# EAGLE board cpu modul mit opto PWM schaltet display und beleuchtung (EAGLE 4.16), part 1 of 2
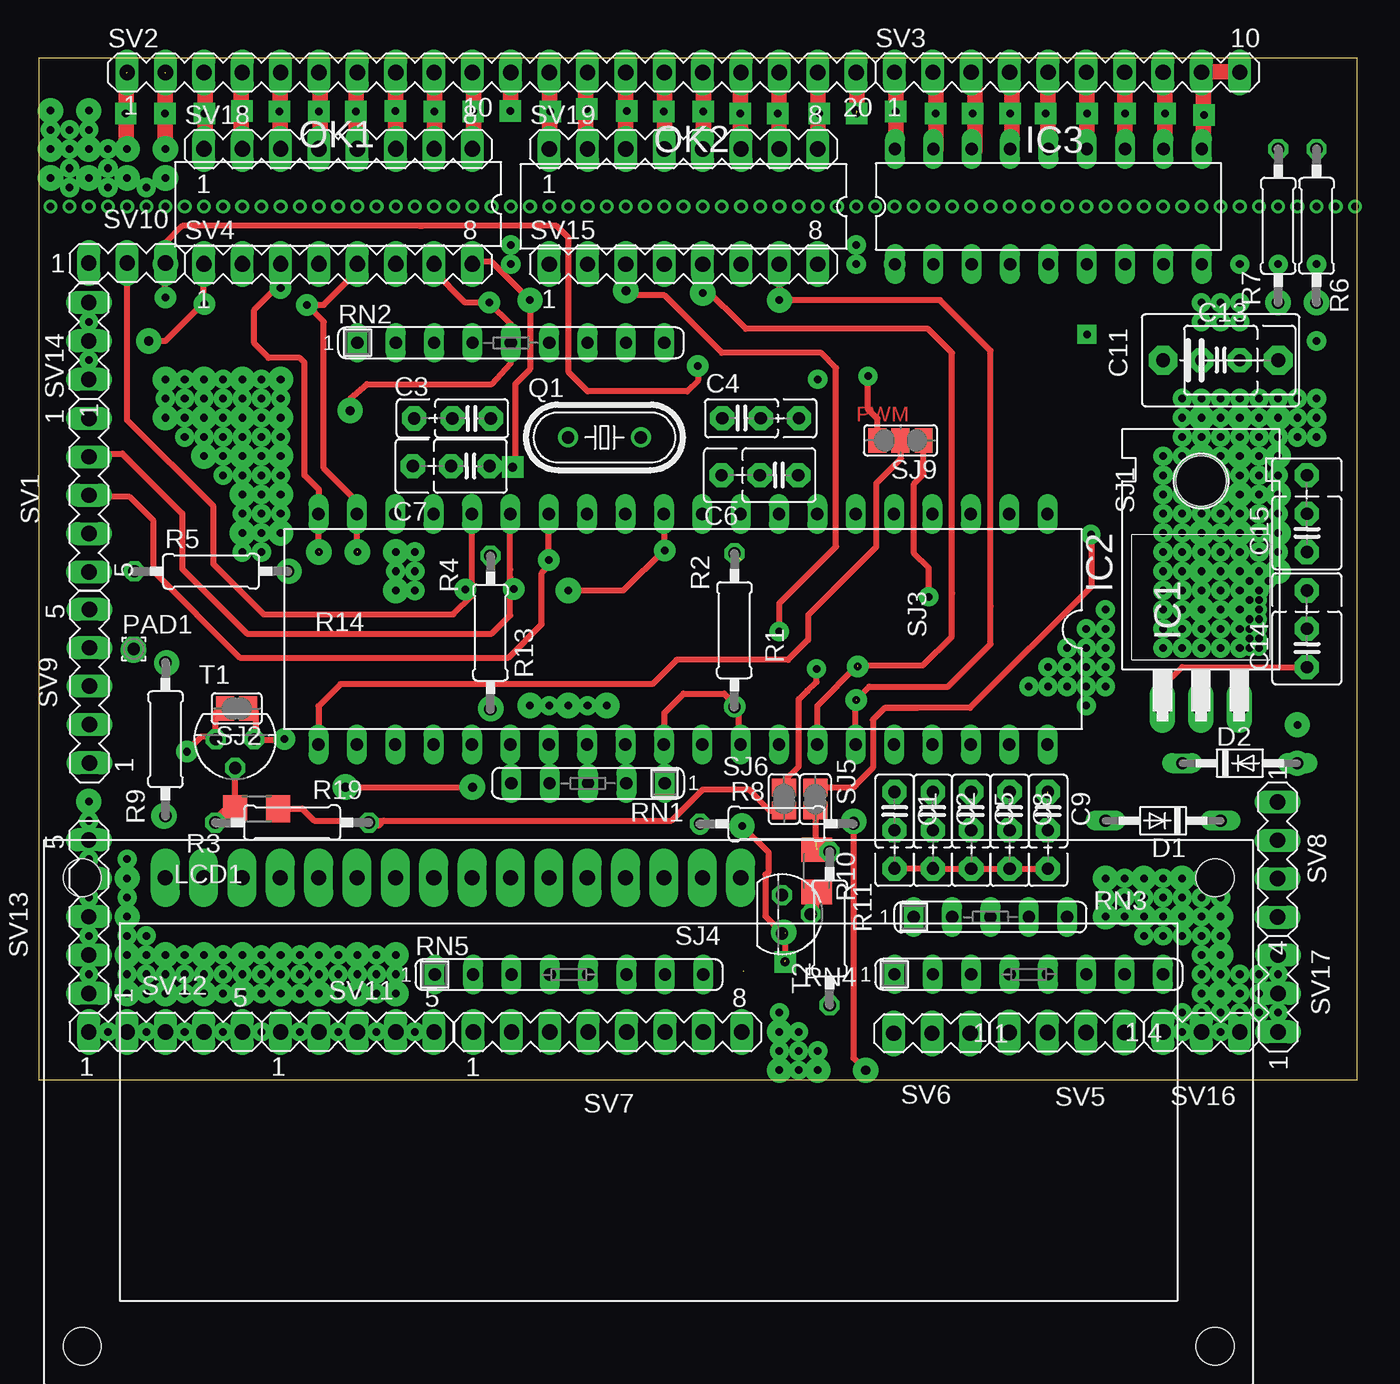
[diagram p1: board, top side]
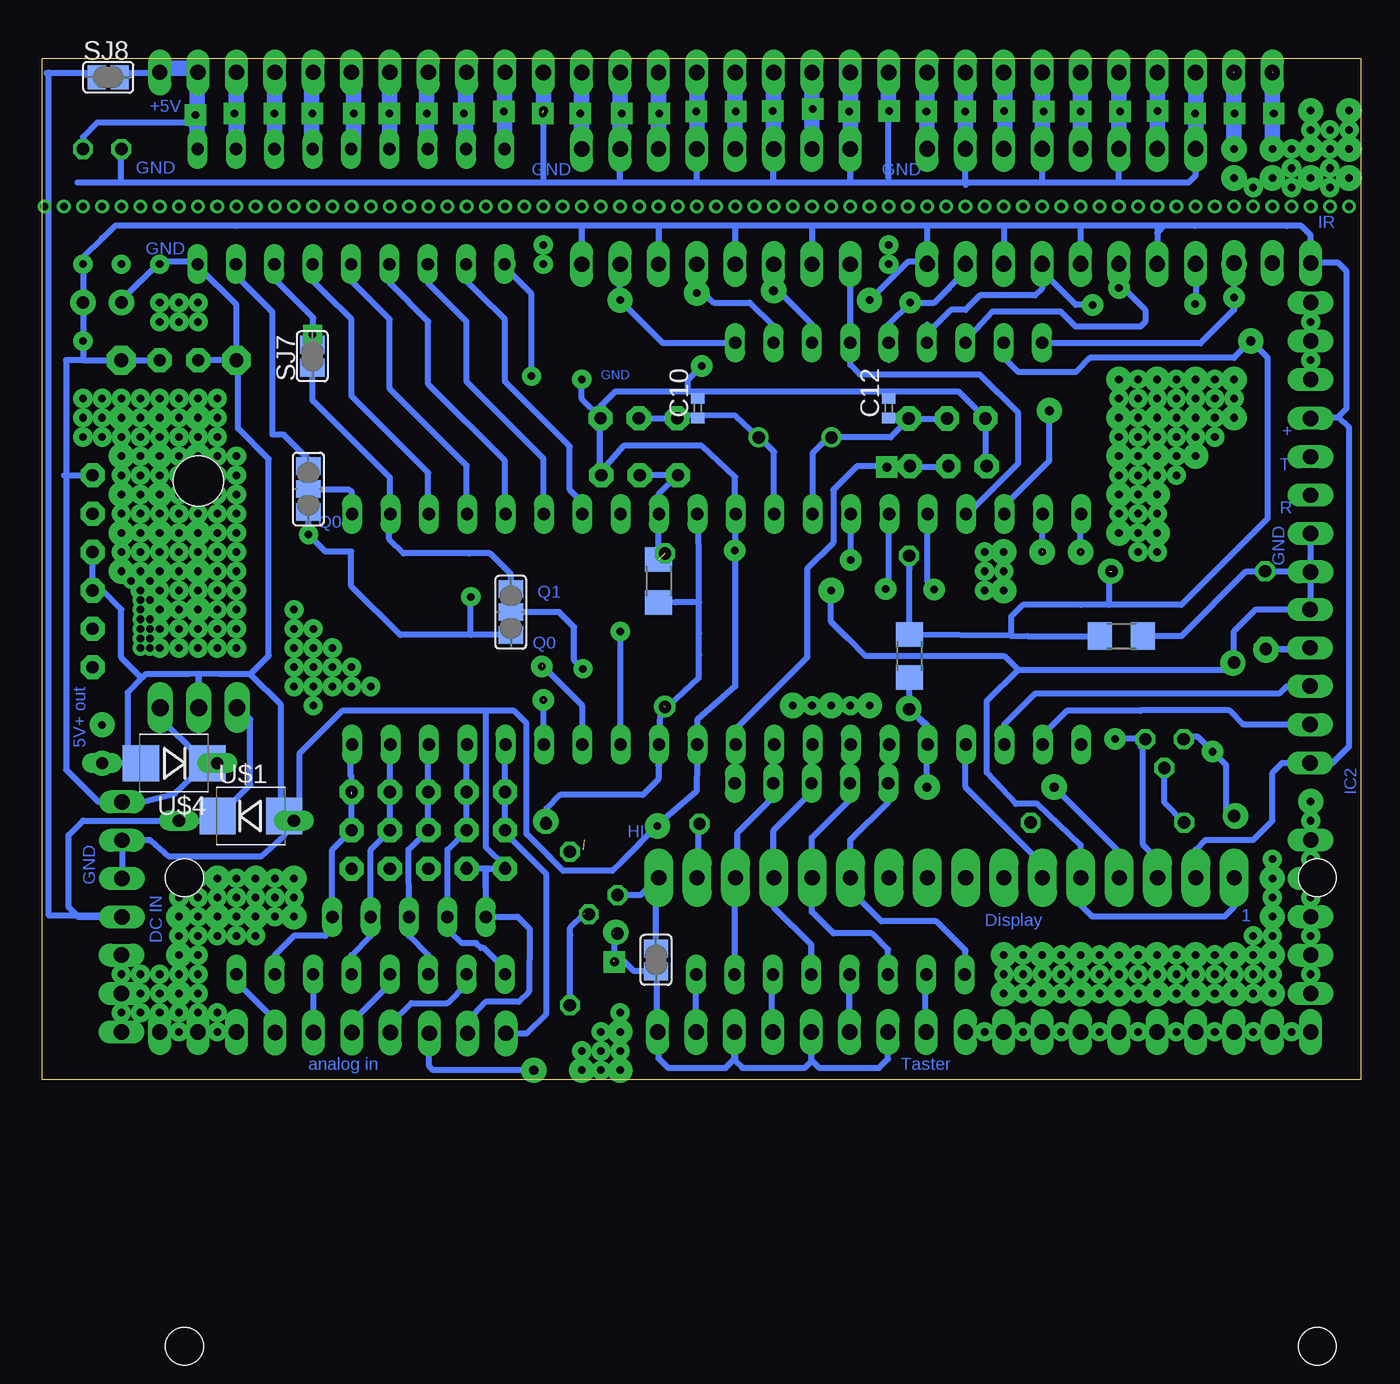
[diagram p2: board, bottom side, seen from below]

Size 87.3 x 67.62 mm. Coordinates in mm from the lower left corner, seen from the top.
Outline: 0,0 87.3,0 87.3,67.62 0,67.62 0,0
Copper layers (1*16): Top 0.035mm / dielectric 1.5mm / Bottom 0.035mm
Design rules "default": minimum track width 10mil, minimum drill 24mil, track to track 8mil, track to pad 8mil, pad to pad 8mil, via to via 8mil, smd to smd 8mil, copper to edge 40mil, drill to drill 8mil, minimum pad ring 10mil, minimum via ring 8mil, stop-mask expansion 4mil, vias tented up to drill 0mil, thermal gap 10mil
Net classes: 0 default: width 0.406 mm, drill 0.254 mm

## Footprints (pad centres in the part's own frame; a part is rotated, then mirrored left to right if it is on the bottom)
C2.5/5-2 = drill 0.813 pad 1.6 octagon: 1 -1.27,0; 2 1.27,0; 3 3.81,0
C2.5/5-4 = drill 0.813 pad 1.6 octagon: 1 -1.27,0; 2 1.27,0; 3 3.81,0
C1005 = smd 0.7 x 0.9: 1 -0.65,0; 2 0.65,0
C7.5B6 = drill 0.914 pad 1.905 octagon: 1 -3.81,0; 2 3.81,0
C2.5/5-5 = drill 0.813 pad 1.6 octagon: 1 -1.27,0; 2 1.27,0; 3 3.81,0
DO34-7 = drill 0.813 long: A 3.81,0; C -3.81,0
TO220H = drill 1.118 long: 1 -2.54,-10.16; 2 0,-10.16; 3 2.54,-10.16 | hole 3.302: 0,4.826
DIL40 = drill 0.813 long: 1 -24.13,-7.62; 2 -21.59,-7.62; 3 -19.05,-7.62; 4 -16.51,-7.62; 5 -13.97,-7.62; 6 -11.43,-7.62; 7 -8.89,-7.62; 8 -6.35,-7.62; 9 -3.81,-7.62; 10 -1.27,-7.62; 11 1.27,-7.62; 12 3.81,-7.62; 13 6.35,-7.62; 14 8.89,-7.62; 15 11.43,-7.62; 16 13.97,-7.62; 17 16.51,-7.62; 18 19.05,-7.62; 19 21.59,-7.62; 20 24.13,-7.62; 21 24.13,7.62; 22 21.59,7.62; 23 19.05,7.62; 24 16.51,7.62; 25 13.97,7.62; 26 11.43,7.62; 27 8.89,7.62; 28 6.35,7.62; 29 3.81,7.62; 30 1.27,7.62; 31 -1.27,7.62; 32 -3.81,7.62; 33 -6.35,7.62; 34 -8.89,7.62; 35 -11.43,7.62; 36 -13.97,7.62; 37 -16.51,7.62; 38 -19.05,7.62; 39 -21.59,7.62; 40 -24.13,7.62
DIL18 = drill 0.813 long: 1 -10.16,-3.81; 2 -7.62,-3.81; 3 -5.08,-3.81; 4 -2.54,-3.81; 5 0,-3.81; 6 2.54,-3.81; 7 5.08,-3.81; 8 7.62,-3.81; 9 10.16,-3.81; 10 10.16,3.81; 11 7.62,3.81; 12 5.08,3.81; 13 2.54,3.81; 14 0,3.81; 15 -2.54,3.81; 16 -5.08,3.81; 17 -7.62,3.81; 18 -10.16,3.81
HY-1602F = drill 1 pad 1.93 long: 1 2.54,0; 2 5.08,0; 3 7.62,0; 4 10.16,0; 5 12.7,0; 6 15.24,0; 7 17.78,0; 8 20.32,0; 9 22.86,0; 10 25.4,0; 11 27.94,0; 12 30.48,0; 13 33.02,0; 14 35.56,0; 15 38.1,0; 16 40.64,0 | hole 2.5: -2.96,0; 72.04,0; -2.96,-31; 72.04,-31
DIL16 = drill 0.813 octagon: 1 -8.89,-3.81; 2 -6.35,-3.81; 3 -3.81,-3.81; 4 -1.27,-3.81; 5 1.27,-3.81; 6 3.81,-3.81; 7 6.35,-3.81; 8 8.89,-3.81; 9 8.89,3.81; 10 6.35,3.81; 11 3.81,3.81; 12 1.27,3.81; 13 -1.27,3.81; 14 -3.81,3.81; 15 -6.35,3.81; 16 -8.89,3.81
1,6/0,8 = drill 0.813 pad 1.6 octagon: 1 0,0
HC49/S = drill 0.813 round: 1 -2.413,0; 2 2.413,0
R1206 = smd 1.6 x 1.803: 1 -1.422,0; 2 1.422,0
0207/10 = drill 0.813 octagon: 1 -5.08,0; 2 5.08,0
M1206 = smd 1.6 x 2: 1 -1.4,0; 2 1.4,0
SIL5 = drill 0.813 long: 1 -5.08,0; 2 -2.54,0; 3 0,0; 4 2.54,0; 5 5.08,0
SIL9 = drill 0.813 long: 1 -10.16,0; 2 -7.62,0; 3 -5.08,0; 4 -2.54,0; 5 0,0; 6 2.54,0; 7 5.08,0; 8 7.62,0; 9 10.16,0
SIL8 = drill 0.813 long: 1 -8.89,0; 2 -6.35,0; 3 -3.81,0; 4 -1.27,0; 5 1.27,0; 6 3.81,0; 7 6.35,0; 8 8.89,0
SJ_2 = smd 1.168 x 1.6: 1 -1.524,0; 2 0,0; 3 1.524,0
SJ = smd 1.168 x 1.6: 1 -0.762,0; 2 0.762,0
MA05-1 = drill 1.016 long: 1 -5.08,0; 2 -2.54,0; 3 0,0; 4 2.54,0; 5 5.08,0
MA20-1 = drill 1.016 long: 1 -24.13,0; 2 -21.59,0; 3 -19.05,0; 4 -16.51,0; 5 -13.97,0; 6 -11.43,0; 7 -8.89,0; 8 -6.35,0; 9 -3.81,0; 10 -1.27,0; 11 1.27,0; 12 3.81,0; 13 6.35,0; 14 8.89,0; 15 11.43,0; 16 13.97,0; 17 16.51,0; 18 19.05,0; 19 21.59,0; 20 24.13,0
MA10-1 = drill 1.016 long: 1 -11.43,0; 2 -8.89,0; 3 -6.35,0; 4 -3.81,0; 5 -1.27,0; 6 1.27,0; 7 3.81,0; 8 6.35,0; 9 8.89,0; 10 11.43,0
MA08-1 = drill 1.016 long: 1 -8.89,0; 2 -6.35,0; 3 -3.81,0; 4 -1.27,0; 5 1.27,0; 6 3.81,0; 7 6.35,0; 8 8.89,0
MA04-1 = drill 1.016 long: 1 -3.81,0; 2 -1.27,0; 3 1.27,0; 4 3.81,0
MA03-1 = drill 1.016 long: 1 -2.54,0; 2 0,0; 3 2.54,0
TO92 = drill 0.813 octagon: 1 1.27,0; 2 0,1.905; 3 -1.27,0
SMB = smd 2.4 x 2.4: A 2.2,0; C -2.2,0

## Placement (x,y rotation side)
C1  [C2.5/5-2]  56.67,17.78 270 top
C2  [C2.5/5-2]  59.21,17.78 270 top
C3  22pf  [C2.5/5-2]  28.67,43.76 180 top
C4  22pf  [C2.5/5-2]  46.54,43.78 0 top
C5  [C2.5/5-2]  61.75,17.78 270 top
C6  100n  [C2.5/5-4]  49.02,40.01 180 top
C7  100n  [C2.5/5-4]  28.59,40.61 180 top
C8  [C2.5/5-2]  64.29,17.78 270 top
C9  [C2.5/5-2]  66.83,17.78 270 top
C10  [C1005]  43.9,44.45 90 bottom
C11  [C7.5B6]  78.26,47.62 0 top
C12  [C1005]  31.26,44.45 90 bottom
C13  [C2.5/5-5]  78.26,47.62 0 top
C14  [C2.5/5-5]  83.97,28.57 90 top
C15  [C2.5/5-5]  83.97,36.19 90 top
D1  BAT81  [DO34-7]  74.45,17.14 180 top
D2  BAT81  [DO34-7]  79.53,20.95 0 top
IC1  7805T  [TO220H]  76.95,34.79 0 top
IC2  MEGA163LP  [DIL40]  42.66,29.81 180 top
IC3  [DIL18]  66.86,57.78 0 top
LCD1  LCD_2X16  [HY-1602F]  5.85,13.37 0 top
OK1  PC847  [DIL16]  19.84,57.94 180 top
OK2  PC847  [DIL16]  42.7,57.78 180 top
PAD1  [1,6/0,8]  6.31,28.5 0 top
Q1  [HC49/S]  37.47,42.51 0 top
R1  10k  [R1206]  46.5,33 90 bottom
R2  [0207/10]  46.07,29.75 270 top
R3  [0207/10]  16.79,17.02 180 top
R4  [0207/10]  29.92,29.6 270 top
R5  4K7  [0207/10]  11.42,33.65 0 top
R6  0  [0207/10]  84.61,56.51 90 top
R7  0R  [0207/10]  82.07,56.51 270 top
R8  47R  [0207/10]  48.87,16.94 0 top
R9  220R  [0207/10]  8.41,22.54 90 top
R10  [M1206]  51.51,13.82 270 top
R11  10K  [0207/10]  52.37,10.01 270 top
R13  1K  [R1206]  29.9,28.04 90 bottom
R14  4K7  [R1206]  15.87,29.36 180 bottom
R19  10K  [R1206]  14.44,17.93 180 top
RN1  100K  [SIL5]  36.38,19.62 180 top
RN2  10K  [SIL9]  31.27,48.77 0 top
RN3  4K7  [SIL5]  63.02,10.76 0 top
RN4  4K7  [SIL8]  65.56,6.98 0 top
RN5  [SIL8]  35.12,6.96 0 top
SJ1  [SJ_2]  69.69,39.1 270 bottom
SJ2  [SJ]  13.12,24.56 180 top
SJ3  [SJ_2]  56.28,30.95 90 bottom
SJ4  [SJ]  46.67,7.93 90 bottom
SJ5  [SJ]  51.43,18.57 90 top
SJ6  [SJ]  49.36,18.58 270 top
SJ7  [SJ]  69.42,47.88 90 bottom
SJ8  [SJ]  82.94,66.35 0 bottom
SJ9  [SJ_2]  57.06,42.31 180 top
SV1  [MA05-1]  3.33,38.69 270 top
SV2  [MA20-1]  30,66.66 0 top
SV3  [MA10-1]  68.1,66.67 0 top
SV4  [MA08-1]  19.84,53.97 0 top
SV5  [MA04-1]  68.08,3.12 0 top
SV6  [MA03-1]  59.15,3.07 180 top
SV7  [MA08-1]  37.67,3.15 0 top
SV8  [MA04-1]  82.02,14.58 270 top
SV9  [MA05-1]  3.37,26.05 90 top
SV10  [MA03-1]  5.87,54.05 0 top
SV11  [MA05-1]  21.11,3.17 0 top
SV12  [MA05-1]  8.41,3.17 0 top
SV13  [MA05-1]  3.33,10.79 90 top
SV14  [MA03-1]  3.33,48.89 90 top
SV15  [MA08-1]  42.7,53.97 0 top
SV16  [MA03-1]  76.99,3.17 0 top
SV17  [MA03-1]  82.07,5.71 90 top
SV18  [MA08-1]  19.84,61.59 0 top
SV19  [MA08-1]  42.7,61.59 0 top
T1  BC547  [TO92]  13.01,22.54 180 top
T2  BC547  [TO92]  49.22,10.95 270 top
U$1  [SMB]  73.49,17.46 0 bottom
U$4  [SMB]  78.57,20.95 180 bottom

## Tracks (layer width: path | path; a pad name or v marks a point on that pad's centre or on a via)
GND
  Top 0: C2.3 59.22,13.96 59.26,14 59.3,13.96 | 59.3,13.96 C5.3 | C5.3 C8.3 | C8.3 C9.3 | C5.3 C8.3 | C5.3 61.67,13.96 61.65,13.94 | 59.3,13.96 59.29,13.96 | C5.3 59.29,13.96 | 59.29,13.96 59.26,13.94
  Bottom 0.406: 57.94,13.96 C1.3 | 57.94,12.7 57.94,13.96 | 57.94,13.96 C2.3
N$1
  Bottom 0: C10.1 43.9,43.85 44.02,43.97 45.24,43.97
  Bottom 0.406: C4.1 45.27,43.94 45.24,43.97 41.39,43.93 Q1.2 39.84,42.54 38.85,41.55 IC2.12
N$2  (1 unrouted)
  Bottom 0.406: C6.3 45.23,40.01 46.47,38.76 IC2.9 46.51,37.46 | R1.2 46.51,37.46 | 46.51,37.46
N$3
  Bottom 0: C3.1 29.96,43.77 29.96,43.76 29.99,43.79 C12.1
  Bottom 0.406: IC2.13 36.3,38.63 36.3,41.47 35.24,42.54 35.2,42.51 Q1.1 31.14,42.51 29.88,43.77 | 29.88,43.77 29.84,43.81 | C3.1 29.88,43.77
N$4  (via drill 0.5 pad 1.27, 0.6 pad 1.68)
  Top 0.406: OK2.11 v38.89,52.22 39.2,51.91 41.43,51.91 45.24,48.1 51.8,48.1 52.8,47.1 52.8,35.29 | 52.8,35.29 | 52.8,35.29 49.04,31.53 v49.04,29.67 v49.04,29.66 | v49.04,29.66 49.01,29.64 | v49.04,29.66
  Bottom 0.406: RN2.7 36.35,50.01 38.89,52.54 v38.89,52.22 | v49.04,29.66 49.04,29.63 49.01,29.61 IC2.33
N$5
  Top 0.406: SJ2.2 12.01,24.56 11.72,24.27 11.72,22.51 11.74,22.49 | 11.74,22.49 11.78,22.45 | T1.1 11.74,22.49
  Bottom 0.406: R9.1 8.92,17.5 8.92,20.82 10.79,22.7 11.74,22.7 | 11.74,22.7 | 11.74,22.7 T1.1
N$6  (via drill 0.5 pad 1.68)
  Top 0.406: 43.97,52.54 46.83,49.68 58.89,49.68 60.48,48.1 60.48,32.2 60.49,32.19 60.46,32.15 60.46,29.33 58.55,27.42 54.23,27.42 51.55,24.74 IC2.34 | 43.97,52.54 OK2.13 | 43.97,52.54 v43.97,52.06
  Bottom 0.406: RN2.8 38.89,49.85 40.48,51.43 42.86,51.43 43.97,52.54 43.97,53.81 | v43.97,52.06 43.97,53.81 | 43.97,53.81 OK2.13
N$7
  Bottom 0.406: RN5.7 41.43,8.15 41.43,11.81 LCD1.14 41.31,13.37 41.27,13.33 41.27,16.35 38.92,18.7 RN1.2 38.92,22.19 38.89,22.22 IC2.29
N$8
  Bottom 0.406: IC2.28 36.35,22.22 36.38,22.19 RN1.3 36.38,19.02 38.89,16.5 38.89,13.33 38.87,13.35 LCD1.13 38.87,13.19 38.89,13.17 38.89,11.43 36.39,8.93 RN5.5
N$9
  Bottom 0.406: IC2.27 33.81,22.22 33.84,22.19 RN1.4 33.84,18.54 36.35,16.03 36.35,13.49 36.47,13.37 LCD1.12 36.33,13.35 36.35,13.33 36.35,11.11 34.92,9.68 32.38,9.68 31.31,8.61 RN5.3
N$10
  Bottom 0.406: IC2.26 31.27,21.15 31.27,20.75 RN1.5 31.3,18.38 33.81,15.87 33.81,13.33 | 33.81,13.33 33.79,13.35 LCD1.11 | 33.81,13.33 33.81,12.54 31.74,10.47 28.09,10.47 26.19,8.57 26.19,7.14 26.35,6.98 26.33,6.96 RN5.1
N$11
  Bottom 0.406: R8.1 43.87,16.68 43.87,15.06 LCD1.15
N$12
  Top 0.406: SJ2.1 14.2,24.56 14.4,24.36 14.4,22.69 14.28,22.57 T1.3
  Bottom 0.406: LCD1.3 13.47,13.35 13.49,13.33 13.49,14.6 14.44,15.55 14.44,22.22 14.28,22.38 | 14.28,22.38 14.6,22.06 | 14.28,22.38 | 14.28,22.38 T1.3
N$13
  Bottom 0.406: 59.07,34.84 59.03,34.84 | 59.07,34.84 63.4,34.84 64.33,35.77 64.33,37.47 64.3,37.43 IC2.2 64.29,37.46 64.29,39.84 69.37,44.93 69.39,44.93 69.39,47.12 SJ7.1 69.42,48.66 | SJ3.3 56.28,33.45 57.67,34.83 59.07,34.83 59.07,34.84 | IC3.7 71.94,53.88 71.94,53.87 71.94,53 69.36,50.42 69.36,48.64 SJ7.2 69.42,48.66 | 69.42,48.66 69.39,48.69
N$14
  Bottom 0.406: LCD1.6 21.09,14.26 26.19,19.36 26.19,22.38 26.15,22.34 IC2.24
N$15
  Top 0: R3.2 11.71,17.3 12.46,18.06 12.87,18.06 13.02,17.91 R19.2
  Top 0.406: R19.2 | R19.2 T1.2 | R19.2
N$16
  Bottom 0.406: 10.9,51.36 10.9,54.12
N$17  (via drill 0.6 pad 1.68)  (1 unrouted)
  Top 0.406: v7.3,48.89 8.41,48.89 10.95,51.43 OK1.9 | OK1.9
  Bottom 0: 29.94,34.7 R4.1 29.92,34.65 29.9,34.63
  Bottom 0.406: 23.16,29.38 R13.2 29.9,34.73 | 23.16,29.38 22.06,29.36 R14.2 | R14.2 | R14.2 | 23.16,29.38 23.16,30.64 22.38,31.43 16.66,31.43 | 16.66,31.43 11.9,31.43 6.18,37.14 6.18,47.78 v7.3,48.89 8.41,47.78 17.93,47.78 18.89,46.83 22.69,46.83 23.65,47.78 RN2.2 | 16.66,31.43 16.66,33.65 | 16.66,31.43 18.57,31.43 | 29.9,34.73 29.92,34.71 R4.1 | 29.9,34.73 29.89,34.74
N$18
  Bottom 0.406: IC2.3 61.71,37.49 61.59,37.62 61.75,37.78 61.75,40.16 66.83,45.24 66.83,50.32 68.57,52.06 | 68.57,52.06 | 68.57,52.06 69.37,52.86 69.37,53.97 IC3.6
N$19
  Top 0.406: IC2.14 33.77,34.09 33.31,33.52 33.31,30.16 31.11,27.93 13.33,27.93 7.61,33.65 7.61,36.98 6.03,38.57 3.49,38.57 3.33,38.72 | 3.33,38.72 3.33,38.73 | 3.33,38.72 SV1.3
N$20
  Bottom 0.406: IC2.4 59.21,37.46 59.21,40.63 64.29,45.72 64.29,50.32 66.03,52.06 | 66.03,52.06 | 66.03,52.06 66.83,52.86 66.83,53.97 IC3.5
N$21  (via drill 0.5 pad 1.68)
  Top 0.406: 49.05,52.38 49.84,51.59 59.68,51.59 63.02,48.25 63.02,31.34 63.03,31.33 63.03,28.83 60.21,26.02 54.99,26.02 54.09,25.12 IC2.35 | 49.05,52.38 OK2.15 | 49.05,52.38 v49.05,51.59
  Bottom 0.406: RN2.9 46.23,48.77 v49.05,51.59 49.05,53.65 | 49.05,53.65 OK2.15 49.05,53.65
N$22
  Top 0.406: IC2.15 31.23,33.77 31.23,33.27 31.23,30.73 30.01,29.52 13.81,29.52 9.52,33.81 9.52,37.46 5.55,41.43 3.65,41.43 3.44,41.22 SV1.2
N$23
  Bottom 1.016: 56.7,61.7 56.7,66.65 56.63,66.72
N$24
  Top 0.406: 26.19,53.65 26.19,54.13
N$25
  Bottom 0.406: IC2.5 56.67,37.46 56.67,40.95 61.75,46.04 61.75,50.17 64.29,52.7 64.29,53.81 64.45,53.97 IC3.4
N$26
  Bottom 0.406: IC2.6 54,37.43 53.97,37.46 54.13,37.62 54.13,41.11 59.21,46.2 59.21,50.17 61.75,52.7 61.75,53.81 61.78,53.84 IC3.3
N$27
  Bottom 0.406: 52.54,42.06 56.67,46.2 56.67,50.32 58.41,52.06 | 52.54,42.06 | 52.54,42.06 52.38,41.9 52.38,39.05 51.59,38.25 51.59,37.62 51.75,37.46 51.72,37.43 IC2.7 | 58.41,52.06 | 58.41,52.06 59.21,52.86 59.21,53.97 IC3.2
N$28  (via drill 0.5 pad 1.42)
  other vias: 10.97,51.34
N$29
  Bottom 0.406: 26.19,53.65 26.19,54.13
N$30
  Bottom 0.406: 38.89,52.38 38.89,53.97
N$31
  Bottom 0.406: 33.97,53.97 33.91,54.03 | 33.97,53.97 33.81,53.82 RN2.6 33.81,47.31 33.17,46.67 25.24,46.67 22.69,44.13 22.69,40.79 26.06,37.43 IC2.17 | 33.97,53.97 OK2.9 | 33.97,53.97
N$32  (1 unrouted)
  Bottom 0.406: IC2.40 66.87,21.31 66.87,20.09 66.83,20.09 C9.1 | RN4.7 71.91,8.25 70.64,9.52 68.57,9.52 68.1,10 RN3.5 68.1,15.23 66.83,16.5 66.83,18.89
N$33
  Bottom 0.406: RN4.5 66.83,8.25 65.56,9.52 65.56,10.63 65.43,10.76 | 65.43,10.76 65.4,10.79 65.4,11.11 65.56,11.27 65.56,15.23 64.29,16.5 C8.1 64.29,22.19 IC2.39 | 65.43,10.76 RN3.4 | IC2.39 64.29,22.22 | IC2.39
N$34
  Bottom 0.406: IC2.38 61.75,21.15 C5.1 61.75,16.5 63.06,15.23 RN3.3 63.02,9.52 61.75,8.25 RN4.3
N$35
  Bottom 0.406: IC2.37 59.17,22.1 59.21,22.06 C2.1 59.21,16.5 60.48,15.22 RN3.2 60.53,9.77 60.26,9.77 59.52,9.04 58.57,9.04 58.26,8.73 58.1,8.73 56.67,7.3 RN4.1
N$36
  Bottom 0.406: IC2.36 56.67,22.22 | IC2.36 | 56.61,3.11 56.67,3.17 56.67,3.09 | SV6.3 56.67,3.09 | SV6.3 | 56.67,3.09 55.2,3.09 53.93,4.34 53.93,13.61 56.67,16.35 C1.1 56.67,22.19 IC2.36 | SV6.3 56.67,3.07 56.67,3.09
N$37
  Bottom 0.406: SV5.1 64.27,3.67 62.86,5.08 60.48,5.08 59.21,6.34 RN4.2
N$38
  Bottom 0.406: SV5.2 66.81,3.83 64.76,5.87 | 64.76,5.87 | 64.76,5.87 64.29,6.34 64.29,6.82 64.45,6.98 RN4.4
N$39
  Bottom 0.406: SV5.3 69.35,6.96 RN4.6
N$40
  Bottom 0.406: SV5.4 71.89,3.94 74.29,6.34 74.29,6.66 74.61,6.98 RN4.8
N$41
  Bottom 0.406: RN5.2 28.83,5.71 28.83,4.49 SV7.1
N$42
  Bottom 0.406: SV7.3 33.83,3.15 33.81,3.17 33.85,3.21 RN5.4
N$43
  Bottom 0.406: RN5.6 38.99,5.71 38.99,4.49 SV7.5
N$44
  Bottom 0.406: 44.11,6.96 44.13,6.98 | 44.11,6.96 RN5.8 | SV7.7 44.02,6.87 44.11,6.96
N$45
  Top 0.406: IC1.1 74.41,26 75.72,27.3 C14.1
  Bottom 0.406: U$1.C 74.75,18.31 73.53,19.53 73.53,23.85 74.31,24.63 IC1.1 | U$1.C 76.31,17.65 | SV8.4 84.9,10.77 85.56,11.43 85.56,16.19 84.61,17.14 75.72,17.14 75.69,17.16 U$1.C
N$46
  Bottom 0.406: 4.88,26 4.85,26.03 SV9.3 | IC2.23 23.61,23.52 21.58,25.55 5.39,25.55 4.92,26.03 4.88,26 | 4.88,26
N$47
  Bottom 0.406: IC2.22 20.7,23.19 19.48,24.4 14.61,24.4 14.61,24.44 14.6,24.44 8.73,24.44 7.79,23.51 SV9.2
N$48  (via drill 0.6 pad 1.68)
  Top 0.406: v20.31,19.36 v28.73,19.36
  Bottom 0: R4.2 29.85,24.52 29.83,24.5 29.83,24.4 28.92,23.49 28.73,23.49
  Bottom 0.406: LCD1.4 16.01,15.06 v20.31,19.36 | 28.73,22.38 28.69,22.34 IC2.25 | v28.73,19.36 28.73,22.38 | R13.1 29.9,24.54 29.48,24.14 28.73,23.49 28.73,22.38
N$49
  Bottom 0.406: 5.26,28.47 4.85,28.47 SV9.4 3.47,28.59 3.55,28.5 PAD1.1
N$50
  Top 0.406: IC2.16 28.69,32.03 27.46,30.79 14.92,30.79 11.58,34.13 11.58,37.94 5.87,43.65 SV10.2
N$51  (via drill 0.5 pad 1.68)
  other vias: 3.33,18.41
N$52  (via drill 0.6)
  other vias: 46.51,3.17
N$53  (via drill 0.5 pad 1.42)
  Top 0.406: 8.4,53 v8.4,51.77 8.4,51.37
N$54  (via drill 0.5 pad 1.42)
  other vias: 56.67,53.97
N$55
  Bottom 0.406: 28.57,22.38 28.57,23.17 30,24.6
N$56
  Bottom 0.406: 29.88,33.86 29.89,34.82
N$57
  Top 0.406: 11.74,16.98 11.74,17.3 12.85,18.41 13.01,18.41 13.17,18.25 13.01,18.25
N$58  (via drill 0.5 pad 1.68)
  other vias: 8.41,46.35
N$59  (via drill 0.6)
  other vias: 68.1,10.79
N$60  (via drill 0.5 pad 1.68)
  other vias: 10.95,46.35
N$61  (via drill 0.5)
  other vias: 49.05,37.46
N$62  (via drill 0.5 pad 1.68)
  other vias: 13.49,46.35
N$63  (via drill 0.5 pad 1.68)
  other vias: 16.03,46.35
N$64  (via drill 0.5 pad 1.68)
  other vias: 16.03,43.81
N$65  (via drill 0.5 pad 1.68)
  other vias: 16.03,41.27
N$66  (via drill 0.5 pad 1.68)
  other vias: 16.03,38.73
N$67  (via drill 0.5 pad 1.42, 0.6)
  Top 0.406: IC2.20 18.57,37.46 18.57,39.05 17.77,39.84 | 17.77,39.84 | 17.77,39.84 17.62,40 17.62,47.46 17.3,47.78 15.23,47.78 14.28,48.73 14.28,50.95 15.71,52.38 v16.03,52.38 v16.03,53.97
  Bottom 0.406: RN2.3 26.19,48.88 24.4,50.84 19.88,50.84 18.89,49.84 14.6,49.84 14.28,50.16 14.28,50.95 15.71,52.38 v16.03,52.38 OK1.11 | OK1.11
N$68  (via drill 0.6)
  other vias: 3.33,43.81
N$69  (via drill 0.6)
  other vias: 71.91,3.17
N$70  (via drill 0.6)
  other vias: 82.07,18.41
N$71  (via drill 0.5 pad 1.68)
  other vias: 13.49,38.73
N$72  (via drill 0.5 pad 1.68)
  other vias: 13.49,41.27
N$73  (via drill 0.5 pad 1.68)
  other vias: 13.49,43.81
N$74  (via drill 0.5 pad 1.68)
  other vias: 10.95,43.81
N$75  (via drill 0.5 pad 1.68)
  other vias: 8.41,43.81
N$76  (via drill 0.5 pad 1.68)
  other vias: 10.95,41.27
N$77  (via drill 0.5 pad 1.68)  (2 unrouted)
  Top 0.406: 18.57,34.98 18.55,34.98 18.55,37.49
  Bottom 0.406: 18.55,37.35 18.57,37.35 18.57,34.9
  other vias: 18.57,34.92
N$78  (via drill 0.5 pad 1.68)  (2 unrouted)
  Top 0.406: 21.14,34.96 21.08,34.96 21.08,37.49
  Bottom 0.406: 21.08,34.9 21.08,37.43
  other vias: 21.11,34.92
N$79  (via drill 0.5 pad 1.68)
  other vias: 23.65,34.92
N$80
  Bottom 0.406: 13.05,20.65 13.05,18.38 11.68,17.02
N$81  (via drill 0.5 pad 1.42)
  Top 0.406: 9.82,21.77 9.84,21.77 10.79,22.73 11.73,22.73 11.8,22.66
  other vias: 9.82,21.71
N$82  (via drill 0.5 pad 1.68)
  other vias: 23.65,32.38
N$83  (via drill 0.5 pad 1.68)
  other vias: 13.49,36.19
N$84  (via drill 0.5 pad 1.68)
  other vias: 16.03,36.19
N$85  (via drill 0.5 pad 1.68)
  other vias: 5.87,10.79
N$86  (via drill 0.5 pad 1.68)
  other vias: 5.87,8.25
N$87  (via drill 0.5 pad 1.68)
  other vias: 5.87,5.71
N$88  (via drill 0.5 pad 1.68)
  other vias: 8.41,5.71
N$89  (via drill 0.5 pad 1.68)
  other vias: 10.95,5.71
N$90  (via drill 0.5 pad 1.68)
  other vias: 13.49,5.71
N$91  (via drill 0.5 pad 1.68)
  other vias: 16.03,5.71
N$92  (via drill 0.5 pad 1.68)
  other vias: 18.57,5.71
N$93  (via drill 0.5 pad 1.68)
  other vias: 21.11,5.71
N$94  (via drill 0.5 pad 1.68)
  other vias: 23.65,5.71
N$95  (via drill 0.5 pad 1.68)
  other vias: 23.65,8.25
N$96  (via drill 0.5 pad 1.68)
  other vias: 21.11,8.25
N$97  (via drill 0.5 pad 1.68)
  other vias: 18.57,8.25
N$98  (via drill 0.5 pad 1.68)
  other vias: 16.03,8.25
N$99  (via drill 0.5 pad 1.68)
  other vias: 13.49,8.25
N$100  (via drill 0.5 pad 1.68)
  other vias: 10.95,8.25
N$101  (via drill 0.5 pad 1.68)
  other vias: 8.41,8.25
N$102  (via drill 0.5 pad 1.68)
  other vias: 5.87,13.33
N$103  (via drill 0.5 pad 1.27)  (1 unrouted)
  Top 0: 50.95,30.75 50.95,30.81 55.41,35.28 55.41,39.4 57.11,41.09 57.11,42.4 | R3.1 21.87,17.01 22.05,16.82 22.06,16.82
  Top 0.406: IC2.21 18.53,24.73 20,26.19 40.63,26.19 42.22,27.78 42.22,27.79 49.62,27.79 50.95,29.12 50.95,30.75 55.47,35.27 55.47,39.47 57.1,41.11 57.1,42.35 SJ9.2 | 54.13,19.52 54.06,19.46 | 54.13,19.52 55.24,20.63 55.24,23.81 56.03,24.6 | SJ5.2 51.43,19.36 51.33,19.46 | 54.13,19.52 | SJ5.2 53.94,19.33 54.13,19.52 | 56.03,24.6 58.21,24.6 | 56.03,24.6 61.67,24.6 69.71,32.64 69.71,36.14 69.67,36.1 v69.67,36.08 | v58.93,31.96 58.93,33.87 57.96,34.84 57.96,39.43 58.59,40.07 SJ9.1 58.56,42.31 58.47,42.4 57.11,42.4 | v51.51,27.19 51.51,26.31 50.92,25.73 50.9,25.75 50.34,25.19 50.34,20.72 49.36,19.75 SJ6.1 49.36,19.31 49.34,19.29 49.36,19.27 SJ6.2 48.43,17.82 47.04,19.21 43.98,19.21 43.84,19.06 43.83,19.07 | R19.1 17.46,17.93 18.25,17.14 22.85,17.14 | 22.85,17.14 41.9,17.14 43.83,19.07 | 43.83,19.07 43.97,19.2 | 22.06,16.82 22.54,16.82 22.85,17.14 | 43.97,19.2 | 43.83,19.07 | SJ5.2 51.46,19.29 51.43,19.26 SJ5.1 51.45,17.81 | 51.45,17.81 51.45,17.93 | R11.1 51.45,15.89 51.45,17.81
  Bottom 0: 52.09,29.95 52.09,30.02 53.03,30.96 56.26,30.96
  Bottom 0.305: 56.26,29.43 56.27,29.42 SJ3.1
  Bottom 0.406: v69.67,36.08 68.54,34.95 66.84,34.95 66.84,32.67 63.6,29.44 58.89,29.44 | v69.67,36.08 69.67,37.52 69.69,37.54 SJ1.3 69.69,37.35 69.72,37.31 69.67,37.26 v69.67,36.08 | SJ3.1 56.23,29.42 56.22,29.44 58.89,29.44 | 58.89,29.44 58.89,29.5 58.93,29.54 v58.93,31.96 | SJ3.2 53.09,30.95 52.09,29.95 52.09,27.77 v51.51,27.19 | 56.26,30.96 56.26,29.43
N$104  (via drill 0.5 pad 1.68)
  other vias: 70.64,13.33
N$105  (via drill 0.5 pad 1.68)
  other vias: 73.18,13.33
N$106  (via drill 0.5 pad 1.68)
  other vias: 75.72,13.33
N$107  (via drill 0.5 pad 1.68)
  other vias: 78.26,13.33
N$108  (via drill 0.5 pad 1.68)
  other vias: 78.26,10.79
N$109  (via drill 0.5 pad 1.68)
  other vias: 75.72,10.79
N$110  (via drill 0.5 pad 1.68)
  other vias: 73.18,10.79
N$111  (via drill 0.5 pad 1.68)
  other vias: 70.64,10.79
N$112  (via drill 0.5 pad 1.68)
  other vias: 78.26,8.25
N$113  (via drill 0.5 pad 1.68)
  other vias: 78.26,5.71
N$114  (via drill 0.5 pad 1.27)
  other vias: 74.45,28.57
N$115  (via drill 0.5 pad 1.27)
  other vias: 76.99,28.57
N$116  (via drill 0.5 pad 1.27)
  other vias: 79.53,28.57
N$117  (via drill 0.5 pad 1.27)
  other vias: 80.8,32.38
N$118  (via drill 0.5 pad 1.02)
  other vias: 80.8,31.11
N$119  (via drill 0.5 pad 1.68)
  other vias: 79.53,31.11
N$120  (via drill 0.5 pad 1.68)
  other vias: 76.99,31.11
N$121  (via drill 0.5 pad 1.27)
  other vias: 74.45,31.11
N$122  (via drill 0.5 pad 1.27)
  other vias: 74.45,33.65
N$123  (via drill 0.5 pad 1.68)
  other vias: 76.99,33.65
N$124  (via drill 0.5 pad 1.68)
  other vias: 79.53,33.65
N$125  (via drill 0.5 pad 1.68)
  other vias: 82.07,33.65
N$126  (via drill 0.5 pad 1.68)
  other vias: 82.07,36.19
N$127  (via drill 0.5 pad 1.68)
  other vias: 79.53,36.19
N$128  (via drill 0.5 pad 1.68)
  other vias: 76.99,36.19
N$129  (via drill 0.5 pad 1.27)
  other vias: 74.45,36.19
N$130  (via drill 0.5 pad 1.27)
  other vias: 74.45,38.73
N$131  (via drill 0.5 pad 1.68)
  other vias: 76.99,38.73
N$132  (via drill 0.5 pad 1.68)
  other vias: 79.53,38.73
N$133  (via drill 0.5 pad 1.68)
  other vias: 82.07,38.73
N$134  (via drill 0.5 pad 1.68)
  other vias: 82.07,41.27
N$135  (via drill 0.5 pad 1.68)
  other vias: 79.53,41.27
N$136  (via drill 0.5 pad 1.68)
  other vias: 76.99,41.27
N$137  (via drill 0.5 pad 1.27)
  other vias: 74.45,41.27
N$138  (via drill 0.5 pad 1.68)
  other vias: 76.99,43.81
N$139  (via drill 0.5 pad 1.68)
  other vias: 79.53,43.81
N$140  (via drill 0.5 pad 1.68)
  other vias: 82.07,43.81
N$141  (via drill 0.5 pad 1.02)
  other vias: 80.16,30.47
N$142  (via drill 0.5 pad 1.68)
  other vias: 83.34,23.49
N$143  (via drill 0.5 pad 1.02)
  other vias: 80.16,31.75
N$144  (via drill 0.5 pad 1.02)
  other vias: 80.8,31.75
N$145  (via drill 0.5 pad 1.02)
  other vias: 80.16,33.02
N$146  (via drill 0.5 pad 1.02)
  other vias: 81.43,33.02
N$147  (via drill 0.5 pad 1.02)
  other vias: 80.8,30.47
N$148  (via drill 0.5 pad 1.02)
  other vias: 80.8,29.21
N$149  (via drill 0.5 pad 1.02)
  other vias: 80.16,29.21
N$150  (via drill 0.5 pad 1.27)
  other vias: 84.61,43.81
N$151  (via drill 0.5 pad 1.02)
  other vias: 80.16,29.84
N$152  (via drill 0.5 pad 1.02)
  other vias: 80.8,29.84
N$153  (via drill 0.5 pad 1.02)
  other vias: 80.8,28.57
N$154  (via drill 0.5 pad 1.02)
  other vias: 80.16,28.57
N$155  (via drill 0.5 pad 1.27)
  other vias: 76.99,51.43
N$156  (via drill 0.5 pad 1.27)
  other vias: 79.53,51.43
N$157  (via drill 0.5 pad 1.68)
  other vias: 82.07,51.43
N$158  (via drill 0.5 pad 1.68)
  other vias: 84.61,51.43
N$159  (via drill 0.5 pad 1.27)
  other vias: 84.61,48.89
N$160
  Bottom 0.406: 86.87,66.65 86.87,10.85 81.78,10.85
N$161
  Bottom 0.406: 79.54,66.62 82.18,66.62
N$162
  Bottom 0.406: 87.01,66.62 83.81,66.62 83.81,66.58 83.79,66.56
N$163
  Bottom 0.406: 27.39,43.73 29.94,43.73
N$164
  Bottom 0.406: 27.32,40.55 29.84,40.55
N$165
  Bottom 0.406: 45.31,43.75 47.76,43.75
N$166  (via drill 0.5 pad 1.27)
  other vias: 66.83,27.3
N$167
  Bottom 0.406: 47.74,39.99 45.33,39.99 45.31,39.97
N$168  (via drill 0.5 pad 1.42)
  other vias: 41.46,35.04
N$169  (via drill 0.5 pad 1.42)
  other vias: 46.08,24.7
N$170  (via drill 0.5 pad 1.42)
  Top 0.406: 14.2,22.5 16.24,22.5 v16.29,22.55
  Bottom 0.406: 14.31,22.57 16.27,22.57 v16.29,22.55
N$171  (via drill 0.5 pad 1.42)  (1 unrouted)
  Bottom 0.406: 51.59,22.23 51.54,22.23 51.54,24.74 54.22,27.42
  other vias: 54.22,27.34
N$172  (via drill 0.5 pad 1.42)  (1 unrouted)
  Bottom 0.406: 54.11,22.13 54.11,25.14
  other vias: 54.13,25.12
N$173  (via drill 0.5 pad 1.42)
  Bottom 0.406: v33.77,34.39 33.77,37.45
N$174  (via drill 0.5 pad 1.42)
  Bottom 0.406: 31.52,32.53 31.52,32.6 31.24,32.88 31.24,36.95 31.26,36.96
  other vias: 31.46,32.47
N$175  (via drill 0.5 pad 1.42)
  Bottom 0.406: v28.25,32.45 28.25,32.53 28.71,32.99 28.71,37.37 28.65,37.43
N$179  (via drill 0.5 pad 1.68)
  other vias: 32.54,24.76
N$180  (via drill 0.5 pad 1.68)
  other vias: 35.08,24.76
N$181  (via drill 0.5 pad 1.68)
  other vias: 37.62,24.76
N$185  (via drill 0.5 pad 1.68)
  other vias: 29.94,24.56
N$186  (via drill 0.5 pad 1.27)
  other vias: 29.94,34.69
N$187  (via drill 0.5 pad 1.68)
  other vias: 16.58,33.65
N$188  (via drill 0.5 pad 1.27)
  other vias: 6.28,33.65
N$189  (via drill 0.5 pad 1.68)
  other vias: 6.28,28.45
N$190  (via drill 0.5 pad 1.68)
  other vias: 8.31,17.46
N$191  (via drill 0.5 pad 1.68)
  other vias: 8.48,27.58
N$192  (via drill 0.6 pad 1.68)
  other vias: 53.97,17.1
N$193  (via drill 0.5 pad 1.27)
  other vias: 43.78,16.86
N$194
  Top 0.406: 56.71,14.31 56.68,14.35
N$195  (via drill 0.5 pad 1.68)
  other vias: 49.05,3.17
N$196
  Bottom 0.406: 51.31,11.06 51.57,10.8
N$199  (via drill 0.5 pad 1.68)
  other vias: 49.05,0.63
N$200  (via drill 0.5 pad 1.68)
  other vias: 51.59,0.63
N$203  (via drill 0.5 pad 1.27)
  other vias: 66.83,26.03
N$207  (via drill 0.5 pad 1.27)
  other vias: 68.1,27.3
N$208  (via drill 0.5 pad 1.42, 0.6 pad 1.68)
  Top 0.406: v20.63,44.29 20.63,45.08 21.74,46.03 30,46.03 31.27,47.46 31.27,50 v29.84,51.43 28.25,51.43 26.19,53.49
  Bottom 0.406: IC2.18 23.61,37.97 20.63,40.95 v20.63,44.29 20.63,44.45 | 31.27,48.73 31.27,50 v29.84,51.43 28.25,51.43 26.19,53.49 OK1.15 | OK1.15 | 31.27,48.73 RN2.5 | 31.27,48.73 31.27,47.62
N$209  (via drill 0.5 pad 1.42)
  Top 0.406: IC2.19 21.07,38.29 18.89,40.48 18.89,50.16 v17.77,51.27 18.89,51.27 21.11,53.49
  Bottom 0.406: 28.73,49.52 RN2.4 | 28.73,49.52 28.73,49.99 | v17.77,51.27 18.89,51.27 21.11,53.49 | 21.11,53.49 21.11,52.38 21.58,51.91 25.24,51.91 26.19,50.95 27.14,50.95 28.57,49.52 28.73,49.52 | 21.11,53.97 | 21.11,53.97 OK1.13 | 21.11,53.49 21.11,53.97
N$210
  Bottom 0.406: 76.83,61.43 76.99,61.59 IC3.10 77.02,61.46 76.99,61.43 76.99,62.7 77.62,63.34 83.66,63.34 84.61,62.38 R6.2
N$211
  Bottom 0.406: OK1.8 10.95,59.84 11.42,59.37 16.03,59.37 | 16.03,59.37 21.11,59.37 | 21.11,59.37 26.19,59.37 | 26.19,59.37 33.81,59.37 | 33.81,59.37 38.89,59.37 | 38.89,59.37 43.97,59.37 | 43.97,59.37 49.05,59.37 | 49.05,59.37 82.07,59.37 | 82.07,59.37 84.96,59.37 | 16.03,59.37 OK1.6 | 16.03,59.37 | 21.11,59.37 OK1.4 | 21.11,59.37 | 26.19,59.37 26.19,59.21 | 26.19,59.21 OK1.2 | 26.19,59.21 | 33.81,59.37 OK2.8 | OK2.8 | 38.89,59.37 OK2.6 | OK2.6 | 43.97,59.37 OK2.4 | OK2.4 | 49.05,59.37 OK2.2 | OK2.2 | 82.07,59.37 82.07,59.53 | 82.07,59.53 R7.1 | 82.07,59.53 | OK2.2 49.05,64.13 | OK2.4 43.97,64.13 | OK2.6 38.89,64.13 | OK2.8 33.81,64.13
  Bottom 1.016: OK2.8 33.81,66.67 | OK2.6 38.89,66.67 | OK2.4 43.97,66.67 | OK2.2 49.05,66.67
N$214  (via drill 0.5 pad 1.42, 0.6)  (2 unrouted)
  Top 1.016: 54.19,64.08 54.19,66.45
  Bottom 0.406: 54.13,59.69 v54.13,64.13
  Bottom 1.016: v54.13,64.13 54.13,66.67
  other vias: 54.16,63.96
N$215
  Bottom 0.406: 51.59,61.59 51.59,64.13
  Bottom 1.016: 51.59,61.59 51.59,66.67
N$216
  Bottom 0.406: 46.51,61.59 46.51,64.13
  Bottom 1.016: 46.51,61.59 46.51,66.67
N$217
  Bottom 0.406: 41.43,61.59 41.43,64.13
  Bottom 1.016: 41.43,61.59 41.43,66.67
N$218
  Bottom 0.406: 36.35,61.59 36.35,64.13
  Bottom 1.016: 36.35,61.59 36.35,66.67
N$219
  Bottom 0.406: 31.27,59.69 31.27,64.13
  Bottom 1.016: 31.27,64.13 31.27,66.67
N$220
  Bottom 0.406: 28.73,61.59 28.73,64.13
  Bottom 1.016: 28.73,61.59 28.73,66.67
N$221
  Bottom 0.406: 26.19,61.59 26.19,64.13
  Bottom 1.016: 26.19,61.59 26.19,66.67
N$222
  Bottom 0.406: 23.65,62.22 23.65,64.13
N$223
  Bottom 0.406: 21.11,61.59 21.11,64.13
  Bottom 1.016: 21.11,61.59 21.11,66.67
N$224
  Bottom 0.406: 18.57,61.59 18.57,64.13
  Bottom 1.016: 18.57,61.59 18.57,66.67
N$225
  Bottom 0.406: 16.03,61.59 16.03,64.13
  Bottom 1.016: 16.03,61.59 16.03,66.67
N$226
  Bottom 0.406: 13.49,61.59 13.49,64.13
  Bottom 1.016: 13.49,61.59 13.49,66.67
N$227
  Bottom 0.406: 10.95,61.59 10.95,64.13
  Bottom 1.016: 10.95,61.59 10.95,66.67
N$228  (via drill 0.5 pad 1.68)  (1 unrouted)
  Top 1.016: 8.39,61.7 8.39,66.65
  Bottom 0.406: v8.41,61.59 8.41,64.13
  Bottom 1.016: v8.41,61.59 8.41,66.67
N$229  (via drill 0.5 pad 1.68)  (1 unrouted)
  Top 1.016: 5.81,61.7 5.81,66.65
  Bottom 0.406: v5.87,61.59 5.87,64.13
  Bottom 1.016: v5.87,61.59 5.87,66.67
N$230  (via drill 0.5 pad 1.68)
  other vias: 3.33,61.59
N$231  (via drill 0.5 pad 1.68)
  other vias: 0.79,61.59
N$232  (via drill 0.5 pad 1.68)
  other vias: 0.79,59.69
N$233  (via drill 0.5 pad 1.68)
  other vias: 3.33,59.69
N$234  (via drill 0.5 pad 1.68)
  other vias: 5.87,59.69
N$235  (via drill 0.5 pad 1.68)
  other vias: 8.41,59.69
N$236  (via drill 0.5 pad 1.68)
  other vias: 3.33,64.13
N$237  (via drill 0.5 pad 1.68)
  other vias: 0.79,64.13
N$238  (1 unrouted)
  Top 0.406: T2.2 51.47,10.95 51.47,13.05 R10.2
  Bottom 0.406: 51.4,10.97 52.36,10.07 52.36,9.57 R11.2
N$239
  Bottom 0.406: 46.55,13.37 LCD1.16 46.55,13.37 | T2.3 47.7,12.22 46.55,13.37 | SJ4.2 46.67,13.25 46.55,13.37
N$240  (via drill 0.5 pad 1.27)
  other vias: 69.37,29.84
N$241  (via drill 0.5 pad 1.27)
  other vias: 69.37,28.57
N$242  (via drill 0.5 pad 1.27)
  other vias: 69.37,27.3
N$243  (via drill 0.5 pad 1.27)
  other vias: 69.37,26.03
N$244  (via drill 0.5 pad 1.27)
  other vias: 69.37,24.76
N$245  (via drill 0.5 pad 1.27)
  other vias: 70.64,26.03
N$246  (via drill 0.5 pad 1.27)
  other vias: 70.64,27.3
N$249  (via drill 0.5 pad 1.27)
  other vias: 70.64,28.57
N$250  (via drill 0.5 pad 1.27)
  other vias: 70.64,29.84
N$253  (via drill 0.5 pad 1.27)
  other vias: 70.64,31.11
N$256  (via drill 0.5 pad 1.27)
  other vias: 68.1,28.57
N$258  (via drill 0.5 pad 1.27)
  other vias: 65.56,26.03
N$259  (via drill 0.5 pad 1.27)
  other vias: 68.1,26.03
N$265  (via drill 0.5 pad 1.27)
  Top 0.406: SJ9.3 55.54,43.74 54.91,44.37 v54.91,46.55 v54.91,46.56 | v54.91,46.56 54.89,46.58 | v54.91,46.56 v54.92,46.56
  Bottom 0.406: IC3.1 56.7,53.79 54.92,52.01 v54.92,46.56
N$266
  Bottom 0.406: IC2.1 66.79,38.87 66.97,39.04 69.59,39.04 69.65,39.1 SJ1.2 SJ1.1 | IC3.8 74.48,53.21 72.23,50.95 | 72.23,50.95 | 72.23,50.95 72.07,50.79 72.07,42.7 71.32,42.7 69.69,41.07 SJ1.1 | SJ1.1 69.71,40.65
N$267  (via drill 0.5 pad 1.27)
  other vias: 9.68,46.35
N$268  (via drill 0.5 pad 1.27)
  other vias: 12.22,46.35
N$269  (via drill 0.5 pad 1.27)
  other vias: 14.76,46.35
N$270  (via drill 0.5 pad 1.27)
  other vias: 14.76,45.08
N$271  (via drill 0.5 pad 1.27)
  other vias: 13.49,45.08
N$272  (via drill 0.5 pad 1.27)
  other vias: 12.22,45.08
N$273  (via drill 0.5 pad 1.27)
  other vias: 10.95,45.08
N$274  (via drill 0.5 pad 1.27)
  other vias: 9.68,45.08
N$275  (via drill 0.5 pad 1.27)
  other vias: 8.41,45.08
N$276  (via drill 0.5 pad 1.27)
  other vias: 9.68,42.54
N$277  (via drill 0.5 pad 1.27)
  other vias: 9.68,43.81
N$278  (via drill 0.5 pad 1.27)
  other vias: 12.22,43.81
N$279  (via drill 0.5 pad 1.27)
  other vias: 12.22,42.54
N$280  (via drill 0.5 pad 1.27)
  other vias: 10.95,42.54
N$281  (via drill 0.5 pad 1.27)
  other vias: 12.22,41.27
N$282  (via drill 0.5 pad 1.27)
  other vias: 12.22,40
N$283  (via drill 0.5 pad 1.27)
  other vias: 13.49,40
N$284  (via drill 0.5 pad 1.27)
  other vias: 14.76,40
N$285  (via drill 0.5 pad 1.27)
  other vias: 16.03,40
N$286  (via drill 0.5 pad 1.27)
  other vias: 16.03,42.54
N$287  (via drill 0.5 pad 1.27)
  other vias: 14.76,42.54
N$288  (via drill 0.5 pad 1.27)
  other vias: 14.76,43.81
N$289  (via drill 0.5 pad 1.27)
  other vias: 13.49,42.54
N$290  (via drill 0.5 pad 1.27)
  other vias: 14.76,41.27
N$291  (via drill 0.5 pad 1.27)
  other vias: 16.03,45.08
N$292  (via drill 0.5 pad 1.27)
  other vias: 14.76,38.73
N$293  (via drill 0.5 pad 1.27)
  other vias: 14.76,37.46
N$294  (via drill 0.5 pad 1.27)
  other vias: 13.49,37.46
N$295  (via drill 0.5 pad 1.27)
  other vias: 16.03,37.46
N$296  (via drill 0.5 pad 1.27)
  other vias: 14.76,36.19
N$297  (via drill 0.5 pad 1.27)
  other vias: 14.76,34.92
N$298  (via drill 0.5 pad 1.27)
  other vias: 13.49,34.92
N$301  (via drill 0.5 pad 1.27)
  other vias: 24.92,34.92
N$302  (via drill 0.5 pad 1.27)
  other vias: 24.92,33.65
N$303  (via drill 0.5 pad 1.27)
  other vias: 24.92,32.38
N$304  (via drill 0.5 pad 1.27)
  other vias: 23.65,33.65
N$309  (via drill 0.5 pad 1.27)
  other vias: 2.06,60.32
N$310  (via drill 0.5 pad 1.27)
  other vias: 2.06,62.86
N$311  (via drill 0.5 pad 1.27)
  other vias: 0.79,62.86
N$312  (via drill 0.5 pad 1.27)
  other vias: 3.33,62.86
N$313  (via drill 0.5 pad 1.27)
  other vias: 2.06,61.59
N$314  (via drill 0.5 pad 1.27)
  other vias: 7.14,59.05
N$315  (via drill 0.5 pad 1.27)
  other vias: 4.6,59.05
N$316  (via drill 0.5 pad 1.27)
  other vias: 2.06,59.05
N$317  (via drill 0.5 pad 1.27)
  other vias: 4.6,60.32
N$318  (via drill 0.5 pad 1.27)
  other vias: 4.6,61.59
N$319  (via drill 0.5 pad 1.27)
  other vias: 7.14,6.98
N$320  (via drill 0.5 pad 1.27)
  other vias: 9.68,6.98
N$321  (via drill 0.5 pad 1.27)
  other vias: 12.22,6.98
N$322  (via drill 0.5 pad 1.27)
  other vias: 14.76,6.98
N$323  (via drill 0.5 pad 1.27)
  other vias: 17.3,6.98
N$324  (via drill 0.5 pad 1.27)
  other vias: 19.84,6.98
N$325  (via drill 0.5 pad 1.27)
  other vias: 22.38,6.98
N$326  (via drill 0.5 pad 1.27)
  other vias: 5.87,12.06
N$327  (via drill 0.5 pad 1.27)
  other vias: 5.87,9.52
N$328  (via drill 0.5 pad 1.27)
  other vias: 5.87,6.98
N$329  (via drill 0.5 pad 1.27)
  other vias: 7.14,5.71
N$330  (via drill 0.5 pad 1.27)
  other vias: 9.68,5.71
N$331  (via drill 0.5 pad 1.27)
  other vias: 12.22,5.71
N$332  (via drill 0.5 pad 1.27)
  other vias: 14.76,5.71
N$333  (via drill 0.5 pad 1.27)
  other vias: 17.3,5.71
N$334  (via drill 0.5 pad 1.27)
  other vias: 19.84,5.71
N$335  (via drill 0.5 pad 1.27)
  other vias: 22.38,5.71
N$336  (via drill 0.5 pad 1.27)
  other vias: 23.65,6.98
N$337  (via drill 0.5 pad 1.27)
  other vias: 22.38,8.25
N$338  (via drill 0.5 pad 1.27)
  other vias: 19.84,8.25
N$339  (via drill 0.5 pad 1.27)
  other vias: 17.3,8.25
N$340  (via drill 0.5 pad 1.27)
  other vias: 14.76,8.25
N$341  (via drill 0.5 pad 1.27)
  other vias: 12.22,8.25
N$342  (via drill 0.5 pad 1.27)
  other vias: 9.68,8.25
N$343  (via drill 0.5 pad 1.27)
  other vias: 7.14,8.25
N$344  (via drill 0.5 pad 1.27)
  other vias: 8.41,6.98
N$345  (via drill 0.5 pad 1.27)
  other vias: 10.95,6.98
N$346  (via drill 0.5 pad 1.27)
  other vias: 13.49,6.98
N$347  (via drill 0.5 pad 1.27)
  other vias: 16.03,6.98
N$348  (via drill 0.5 pad 1.27)
  other vias: 18.57,6.98
N$349  (via drill 0.5 pad 1.27)
  other vias: 21.11,6.98
N$350  (via drill 0.5 pad 1.27)
  other vias: 7.14,9.52
N$351  (via drill 0.5 pad 1.27)
  other vias: 3.33,14.6
N$352  (via drill 0.5 pad 1.27)
  other vias: 3.33,12.06
N$353  (via drill 0.5 pad 1.27)
  other vias: 3.33,9.52
N$354  (via drill 0.5 pad 1.27)
  other vias: 3.33,6.98
N$355  (via drill 0.5 pad 1.27)
  other vias: 4.6,3.17
N$356  (via drill 0.5 pad 1.27)
  other vias: 7.14,3.17
N$357  (via drill 0.5 pad 1.27)
  other vias: 9.68,3.17
N$358  (via drill 0.5 pad 1.27)
  other vias: 12.22,3.17
N$359  (via drill 0.5 pad 1.27)
  other vias: 14.76,3.17
N$360  (via drill 0.5 pad 1.27)
  other vias: 17.3,3.17
N$361  (via drill 0.5 pad 1.27)
  other vias: 19.84,3.17
N$362  (via drill 0.5 pad 1.27)
  other vias: 22.38,3.17
N$363  (via drill 0.5 pad 1.27)
  other vias: 24.92,3.17
N$364  (via drill 0.5 pad 1.27)
  other vias: 3.33,17.14
N$365  (via drill 0.5 pad 1.27)
  other vias: 3.33,50.16
N$366  (via drill 0.5 pad 1.27)
  other vias: 3.33,47.62
N$367  (via drill 0.5 pad 1.27)
  other vias: 78.26,51.43
N$368  (via drill 0.5 pad 1.27)
  other vias: 76.99,50.16
N$369  (via drill 0.5 pad 1.27)
  other vias: 78.26,50.16
N$370  (via drill 0.5 pad 1.27)
  other vias: 79.53,50.16
N$371  (via drill 0.5 pad 1.27, 0.5 pad 1.68, 0.6 pad 1.68)  (1 unrouted)
  Top 0.305: 53.95,14.34 53.91,14.34 53.86,14.39
  Top 0.406: 31.39,40.61 C7.1 | 31.39,40.61 31.4,40.61 | 32.38,51.75 v32.54,51.59 32.54,47.03 31.55,46.04 31.55,40.78 31.39,40.62 31.39,40.61 | 32.38,51.75 31.27,52.86 | 46.19,24.76 45.4,25.55 42.7,25.55 41.43,24.28 41.43,22.06 41.39,22.1 IC2.30 | 46.19,24.76 | 46.19,24.76 46.35,24.6 46.35,22.38 46.47,22.25 IC2.32 | 54.02,1.38 53.95,1.44 | 54.02,1.38 v54.76,0.63 | OK1.16 30,54.13 32.38,51.75 | 54.02,1.38 53.95,1.45 53.95,14.34 53.95,14.39 | R8.2 53.95,14.39 | 53.95,14.39
  Bottom 0: 84.58,51.38 84.61,51.41 R6.1
  Bottom 0.406: 8.41,15.87 8.1,15.87 | 76.96,21.15 77.19,21.15 77.06,21.12 | 77.06,21.12 U$4.C 78.53,18.91 80.65,18.39 81.01,18.39 SV8.1 83.6,18.4 85.73,20.52 85.73,40 | 43.83,28.09 43.83,26.6 46.37,24.21 IC2.32 46.46,20.84 46.51,20.79 46.51,19.88 47.54,18.85 53.03,18.85 53.93,17.94 53.93,17.04 54.01,16.96 53.98,16.94 R8.2 | 43.83,28.09 43.83,30 | 43.83,30 43.83,34.72 43.87,36.19 IC2.10 | 4.92,56.51 11,56.51 | 4.92,56.51 4.85,56.51 | 11,56.51 13.49,56.51 | 13.49,56.51 18.57,56.51 | 18.57,56.51 23.65,56.51 | 23.65,56.51 28.73,56.51 | 28.73,56.51 36.35,56.51 | 36.35,56.51 41.43,56.51 | 41.43,56.51 46.51,56.51 | 46.51,56.51 51.59,56.51 | 51.59,56.51 74.45,56.51 | 74.45,56.51 82.47,56.51 83.29,55.7 83.32,55.7 | 34.76,39.2 34.93,39.03 34.93,35.55 36.66,33.81 36.66,27.93 39.36,25.24 | 34.76,39.2 34.52,39.44 | 51.59,56.51 51.59,56.5 OK2.16 | 5.21,20.97 SV9.1 | 5.21,20.97 5.87,20.32 5.87,17.14 7.14,15.87 8.41,15.87 | 8.41,15.87 10.31,15.87 10.95,15.23 10.95,13.33 10.93,13.35 LCD1.2 | 41.43,22.22 IC2.30 | RN1.1 41.46,22.19 41.43,22.22 | 43.83,28.09 43.81,28.09 43.81,29.52 | 41.43,22.22 41.43,23.17 39.36,25.24 | 39.36,25.24 | 77.06,21.12 77.06,21.35 76.99,21.43 79.49,23.93 IC1.3 | 83.32,55.7 83.34,55.72 | 85.73,40 85.73,47.62 84.58,47.62 | 84.58,47.62 C11.2 v79.53,47.62 | 5.21,20.97 1.88,20.97 0.79,22.06 0.79,43.17 1.42,43.81 1.58,43.81 | SV1.1 3.44,43.77 3.49,43.81 1.58,43.81 | SV6.1 61.69,0.89 61.43,0.63 v54.76,0.63 | 34.76,39.2 34.76,39.21 33.36,40.61 C7.1 | 43.83,30 43.81,31.59 45.4,31.59 R1.1 | 1.58,43.81 0.95,44.45 0.95,53.49 1.51,54.05 SV10.1 3.33,55.88 3.96,56.51 4.92,56.51 | 32.54,50.95 v32.54,51.59 30,54.13 28.89,54.13
  Bottom 0.406: 74.45,56.51 74.45,56.5 | 11,56.51 13.01,56.51 13.49,56.03 | OK2.16 | OK1.16 29.05,53.81 | 28.73,56.51 OK1.16 | OK1.16 | 28.89,54.13 | OK1.16 28.89,54.13 | 18.57,56.51 OK1.12 | 18.57,56.51 | 13.49,56.51 13.49,56.35 | 13.49,56.35 OK1.10 | 13.49,56.35 | 36.35,53.81 OK2.10 36.35,56.51 | 41.43,56.51 OK2.12 | 46.51,56.51 OK2.14 | OK1.14 | 23.65,56.51 OK1.14 | OK2.16 | OK2.16 51.59,54.13 | 85.73,40 85.88,40 | 85.73,40 C15.3 | 83.32,55.7 83.33,55.7 84.58,54.45 84.58,51.38 84.58,47.62
N$372  (via drill 0.6 pad 1.42)
  other vias: 31.4,40.54
N$373  (via drill 0.5 pad 1.27, 0.5 pad 1.42, 0.5 pad 1.68, 0.6, 0.6 pad 1.42, 0.6 pad 1.68)  (3 unrouted)
  Top 0.406: v35.08,32.38 38.73,32.38 41.43,35.08 41.43,37.3 41.39,37.34 IC2.11 | 8.41,52.86 v8.41,53.97 8.41,55.4 | 8.41,55.4 | 8.41,55.4 9.52,56.51 25.24,56.51 | 25.24,56.51 25.39,56.51 | 25.24,56.51 34.28,56.51 35.08,55.72 35.08,55.68 35.09,55.67 35.09,46.81 36.36,45.55 42.94,45.55 43.64,46.25 v43.64,47.23 | v49.33,9.76 49.18,9.76 48.12,10.82 48.12,13.58 48.14,13.58 48.33,13.76 48.33,15.05 v46.57,16.79 | v59.21,14.12 59.21,13.96 | 59.21,13.96 64.29,13.96 | 59.21,13.96 56.67,13.96 | 59.21,13.96 66.83,13.96 | 49.46,7.9 49.46,9.71
  Bottom 0: 31.31,45.56 31.31,45.53 31.26,45.49 C12.2 | 44.2,45.56 44.2,45.52 43.9,45.22 C10.2 | R5.1 | 7.66,33.6 6.39,33.6 R5.1 | C3.3 24.9,43.77 26.69,45.55 44.54,45.55
  Bottom 0.406: C11.1 74.43,48.38 | 80.71,26.58 80.44,26.84 77.6,26.84 76.95,26.86 IC1.2 76.94,26.85 75.57,26.84 73.53,26.84 | 80.71,26.58 81.66,25.62 81.66,21.97 U$4.A | U$1.A 70.28,17.5 | U$1.A 71.68,17.07 | 73.53,26.84 71.5,24.81 71.5,18.31 U$1.A | 73.53,26.84 72.31,28.06 72.31,41.07 74.35,43.1 74.35,46.76 C11.1 | 57.94,24.4 56.06,24.4 55.25,23.59 55.25,16.28 53.83,14.86 | 57.94,24.4 67.44,24.4 70.28,21.56 70.28,18.31 U$1.A | 53.83,14.86 53.62,14.65 | LCD1.1 8.39,11.45 9.04,10.79 17.77,10.79 18.57,11.58 18.57,13.33 18.55,13.35 LCD1.5 18.55,15.53 21.42,18.25 22.85,18.25 24.77,20.32 24.77,25.07 22.69,27.14 | 36.4,1.26 36.4,1.22 36.82,0.79 40.95,0.79 41.43,1.26 41.43,3.17 41.45,3.15 SV7.6 41.48,1.38 42.06,0.79 45.87,0.79 46.51,1.42 46.51,3.01 46.65,3.15 | 36.4,1.26 SV7.4 | SV7.2 31.32,1.38 31.9,0.79 35.87,0.79 36.35,1.26 36.4,1.26 | 46.65,3.15 46.67,3.17 | 46.65,3.15 SV7.8 | 82.02,13.22 SV8.3 | 82.02,13.22 SV8.2 80.14,15.85 78.89,14.76 72.86,14.76 71.27,16.19 71.27,17.46 U$1.A | 82.02,13.22 82.07,13.17 | 50.32,43.81 50.32,44.6 49.37,45.56 44.2,45.56 31.31,45.56 26.66,45.56 24.87,43.77 C3.3 24.86,40.74 24.76,40.63 C7.3 | SV6.2 59.15,3.86 57.94,5.15 55.76,5.15 55.08,5.84 55.06,10 55.85,10.79 57.94,10.79 | 57.94,10.79 RN3.1 | 57.94,24.4 57.94,15.39 v56.67,14.12 56.67,13.96 57.94,13.96 | 22.69,27.14 9.04,27.14 8.57,27.62 R9.2 8.41,29.68 6.96,31.13 SV9.5 3.33,31.13 | v35.08,32.38 35.08,30.32 34.12,29.36 | 34.12,29.36 | 33.97,29.21 34.12,29.36 | 33.97,29.21 | 33.97,29.21 32.8,28.03 23.59,28.02 22.69,27.14 | SV10.3 v8.41,53.97 8.41,50.95 | 8.41,50.95 10.63,48.73 21.11,48.73 21.11,48.74 | 21.11,48.74 RN2.1
  Bottom 0.406: 21.11,48.74 10.62,48.74 8.41,50.95 | 50.32,43.81 C4.3 50.37,43.1 50.37,40.66 C6.1 49.96,40.66 48.83,41.95 43.64,41.95 41.43,39.9 IC2.11 41.43,36.19 41.43,26.03 43.95,23.82 IC2.31 43.95,21.15 43.99,19.09 46.34,17.06 46.6,16.76 46.56,16.85 47.19,16.21 48.56,14.83 | 50.32,43.81 51.59,45.08 | 51.59,45.08 51.59,45.09 | C11.1 74.45,51.27 77.02,53.84 IC3.9 77.02,53.94 77.15,53.81 77.46,54.13 79.51,54.13 82.07,51.57 R7.2 | 46.65,3.15 46.65,7.15 46.59,7.2 48.15,7.2 49.45,8.5 49.45,9.69 v49.33,9.76 | v49.33,9.76 49.56,9.8 | v49.33,9.76 T2.1 | 53.83,14.86 53.84,14.85 52.82,13.83 49.58,13.83 48.95,14.44 48.56,14.83 | 53.83,14.86 | 48.56,14.83 48.56,14.84 46.83,16.57 v46.57,16.79 | 51.59,45.08 v51.59,46.35 | v59.21,14.12 59.21,13.96 57.94,13.96 | C11.1 v76.99,47.62 | C15.1 C14.3 83.34,32.38 82.07,31.11 82.07,27.93 80.71,26.58 | 3.33,36.18 SV1.4 | SV1.5 3.33,36.18 | 3.33,36.18 3.33,36.19 | SV1.5 7.66,33.6 11.9,29.36 14.28,29.36 | 14.28,29.36 | 14.28,29.36 R14.1 | 3.33,31.13 3.33,31.11 | SV1.5 3.33,31.13 | 57.94,13.96 57.94,10.79 | 44.54,45.55 44.54,46.33 v43.64,47.23
  other vias: 49.42,7.8
N$374
  Bottom 1.016: 59.28,61.5 59.28,66.65
N$375
  Bottom 1.016: 61.86,61.7 61.86,66.93
N$376  (via drill 0.5 pad 1.27)
  other vias: 78.26,45.08
N$377  (via drill 0.5 pad 1.27)
  other vias: 76.99,45.08
N$378  (via drill 0.5 pad 1.27)
  other vias: 75.72,45.08
N$379  (via drill 0.5 pad 1.27)
  other vias: 79.53,45.08
N$380  (via drill 0.5 pad 1.27)
  other vias: 80.8,45.08
N$381  (via drill 0.5 pad 1.27)
  other vias: 82.07,45.08
N$382  (via drill 0.5 pad 1.27)
  other vias: 83.34,45.08
N$383  (via drill 0.5 pad 1.27)
  other vias: 83.34,43.81
N$384  (via drill 0.5 pad 1.27)
  other vias: 83.34,42.54
N$385  (via drill 0.5 pad 1.27)
  other vias: 82.07,42.54
N$386  (via drill 0.5 pad 1.27)
  other vias: 80.8,42.54
N$387  (via drill 0.5 pad 1.27)
  other vias: 80.8,43.81
N$388  (via drill 0.5 pad 1.27)
  other vias: 78.26,42.54
N$389  (via drill 0.5 pad 1.27)
  other vias: 79.53,42.54
N$390  (via drill 0.5 pad 1.27)
  other vias: 78.26,43.81
N$391  (via drill 0.5 pad 1.27)
  other vias: 76.99,42.54
N$392  (via drill 0.5 pad 1.27)
  other vias: 75.72,42.54
N$393  (via drill 0.5 pad 1.27)
  other vias: 75.72,40
N$394  (via drill 0.5 pad 1.27)
  other vias: 75.72,41.27
N$395  (via drill 0.5 pad 1.27)
  other vias: 74.45,40
N$396  (via drill 0.5 pad 1.27)
  other vias: 75.72,38.73
N$397  (via drill 0.5 pad 1.27)
  other vias: 76.99,40
N$398  (via drill 0.5 pad 1.27)
  other vias: 79.53,40
N$399  (via drill 0.5 pad 1.27)
  other vias: 78.26,40
N$400  (via drill 0.5 pad 1.27)
  other vias: 78.26,41.27
N$401  (via drill 0.5 pad 1.27)
  other vias: 78.26,38.73
N$402  (via drill 0.5 pad 1.27)
  other vias: 80.8,38.73
N$403  (via drill 0.5 pad 1.27)
  other vias: 80.8,40
N$404  (via drill 0.5 pad 1.27)
  other vias: 80.8,41.27
N$405  (via drill 0.5 pad 1.27)
  other vias: 82.07,40
N$406
  Bottom 1.016: 64.3,61.7 64.3,66.72 64.51,66.93
N$407
  Bottom 1.016: 66.68,61.7 66.68,66.92 66.88,67.13
N$408
  Bottom 1.016: 69.46,61.7 69.46,66.92 69.26,67.13
N$409
  Bottom 1.016: 71.9,61.7 71.9,66.86 71.84,66.93
N$410
  Bottom 1.016: 74.48,61.7 74.48,66.93
N$411
  Bottom 1.016: 77.06,61.7 77.06,66.45 76.86,66.65
N$412  (via drill 0.5 pad 1.27)
  other vias: 82.07,37.46
N$413  (via drill 0.5 pad 1.27)
  other vias: 80.8,37.46
N$414  (via drill 0.5 pad 1.27)
  other vias: 79.53,37.46
N$415  (via drill 0.5 pad 1.27)
  other vias: 78.26,37.46
N$416  (via drill 0.5 pad 1.27)
  other vias: 76.99,37.46
N$417  (via drill 0.5 pad 1.27)
  other vias: 75.72,37.46
N$418  (via drill 0.5 pad 1.27)
  other vias: 74.45,37.46
N$419  (via drill 0.5 pad 1.27)
  other vias: 74.45,34.92
N$420  (via drill 0.5 pad 1.27)
  other vias: 75.72,34.92
N$421  (via drill 0.5 pad 1.27)
  other vias: 75.72,36.19
N$422  (via drill 0.5 pad 1.27)
  other vias: 78.26,36.19
N$423  (via drill 0.5 pad 1.27)
  other vias: 78.26,34.92
N$424  (via drill 0.5 pad 1.27)
  other vias: 76.99,34.92
N$425  (via drill 0.5 pad 1.27)
  other vias: 76.99,32.38
N$426  (via drill 0.5 pad 1.27)
  other vias: 75.72,32.38
N$427  (via drill 0.5 pad 1.27)
  other vias: 75.72,33.65
N$428  (via drill 0.5 pad 1.27)
  other vias: 74.45,32.38
N$429  (via drill 0.5 pad 1.27)
  other vias: 74.45,29.84
N$430  (via drill 0.5 pad 1.27)
  other vias: 75.72,29.84
N$431  (via drill 0.5 pad 1.27)
  other vias: 75.72,31.11
N$432  (via drill 0.5 pad 1.27)
  other vias: 75.72,28.57
N$433  (via drill 0.5 pad 1.27)
  other vias: 78.26,28.57
N$434  (via drill 0.5 pad 1.27)
  other vias: 78.26,29.84
N$435  (via drill 0.5 pad 1.27)
  other vias: 76.99,29.84
N$436  (via drill 0.5 pad 1.27)
  other vias: 78.26,31.11
N$437  (via drill 0.5 pad 1.27)
  other vias: 78.26,32.38
N$438  (via drill 0.5 pad 1.27)
  other vias: 78.26,33.65
N$439  (via drill 0.5 pad 1.27)
  other vias: 80.8,33.65
N$440  (via drill 0.5 pad 1.27)
  other vias: 80.8,34.92
N$441  (via drill 0.5 pad 1.27)
  other vias: 79.53,34.92
N$442  (via drill 0.5 pad 1.27)
  other vias: 80.8,36.19
N$443  (via drill 0.5 pad 1.27)
  other vias: 82.07,34.92
N$444
  Bottom 1.016: 23.59,61.7 23.59,66.65
N$445
  Bottom 1.016: 76.92,66.93 79.37,66.93
N$446
  Top 1.016: 11.03,61.7 11.03,66.72
N$447
  Top 1.016: 13.41,61.7 13.41,66.65
N$448
  Top 1.016: 15.99,61.7 15.99,66.65
N$449
  Top 1.016: 18.63,61.5 18.63,66.65
N$450
  Top 1.016: 21.01,61.5 21.01,66.65
N$451
  Top 1.016: 23.66,61.7 23.66,66.65
N$452  (via drill 0.5 pad 1.27)
  other vias: 79.53,32.38
N$453  (via drill 0.5 pad 1.27)
  other vias: 79.53,29.84
N$454
  Top 1.016: 26.23,61.7 26.23,66.72
N$455
  Top 1.016: 28.81,61.7 28.81,66.45
N$456
  Top 1.016: 31.26,66.65 31.26,64.28
N$457
  Top 1.016: 33.83,61.7 33.83,66.65
N$458
  Top 1.016: 36.21,61.7 36.21,66.65
N$459
  Top 1.016: 38.86,61.7 38.86,66.65
N$460
  Top 1.016: 41.43,61.7 41.43,66.65
N$461
  Top 1.016: 44.01,61.5 44.01,66.65
N$462
  Top 1.016: 46.46,61.7 46.46,66.45
N$463
  Top 1.016: 49.03,61.7 49.03,66.65
N$464
  Top 1.016: 51.61,61.7 51.61,66.45 51.41,66.65
N$465  (via drill 0.5 pad 1.27)
  other vias: 70.64,12.06
N$466  (via drill 0.5 pad 1.27)
  other vias: 71.91,12.06
N$467  (via drill 0.5 pad 1.27)
  other vias: 74.45,12.06
N$468  (via drill 0.5 pad 1.27)
  other vias: 73.18,12.06
N$469  (via drill 0.5 pad 1.27)
  other vias: 75.72,12.06
N$470  (via drill 0.5 pad 1.27)
  other vias: 78.26,12.06
N$471  (via drill 0.5 pad 1.27)
  other vias: 76.99,12.06
N$472  (via drill 0.5 pad 1.27)
  other vias: 76.99,13.33
N$473  (via drill 0.5 pad 1.27)
  other vias: 74.45,13.33
N$474  (via drill 0.5 pad 1.27)
  other vias: 71.91,13.33
N$475  (via drill 0.5 pad 1.27)
  other vias: 71.91,10.79
N$476  (via drill 0.5 pad 1.27)
  other vias: 74.45,10.79
N$477  (via drill 0.5 pad 1.27)
  other vias: 76.99,10.79
N$478  (via drill 0.5 pad 1.27)
  other vias: 76.99,9.52
N$479  (via drill 0.5 pad 1.27)
  other vias: 75.72,9.52
N$480  (via drill 0.5 pad 1.27)
  other vias: 74.45,9.52
N$481  (via drill 0.5 pad 1.27)
  other vias: 73.18,9.52
N$482  (via drill 0.5 pad 1.27)
  other vias: 78.26,9.52
N$483  (via drill 0.5 pad 1.27)
  other vias: 78.26,6.98
N$484  (via drill 0.5 pad 1.27)
  other vias: 76.99,6.98
N$485  (via drill 0.5 pad 1.27)
  other vias: 76.99,8.25
N$486  (via drill 0.5 pad 1.27)
  other vias: 76.99,5.71
N$487  (via drill 0.5 pad 1.27)
  other vias: 78.26,3.17
N$488  (via drill 0.5 pad 1.27)
  other vias: 75.72,3.17
N$489  (via drill 0.5 pad 1.27)
  other vias: 82.07,4.44
N$490  (via drill 0.5 pad 1.27)
  other vias: 82.07,6.98
N$491  (via drill 0.5 pad 1.27)
  other vias: 79.53,6.98
N$492  (via drill 0.5 pad 1.27)
  other vias: 80.8,6.98
N$493  (via drill 0.5 pad 1.27)
  other vias: 79.53,5.71
N$494  (via drill 0.5 pad 1.27)
  other vias: 80.8,4.44
N$495  (via drill 0.5 pad 1.27)
  other vias: 78.26,4.44
N$496  (via drill 0.5 pad 1.27)
  other vias: 76.99,4.44
N$497  (via drill 0.5 pad 1.27)
  other vias: 79.53,4.44
N$498  (via drill 0.5 pad 1.27)
  other vias: 80.8,5.71
N$499  (via drill 0.5 pad 1.27)
  other vias: 75.72,4.44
